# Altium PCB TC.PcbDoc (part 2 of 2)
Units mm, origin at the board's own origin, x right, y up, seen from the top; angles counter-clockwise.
Board outline 53.6 x 100 mm, 2 copper layers (Top Layer, Bottom Layer), stack 1.554 mm thick; 127 components, 95 nets, 328 pads, 171 vias.
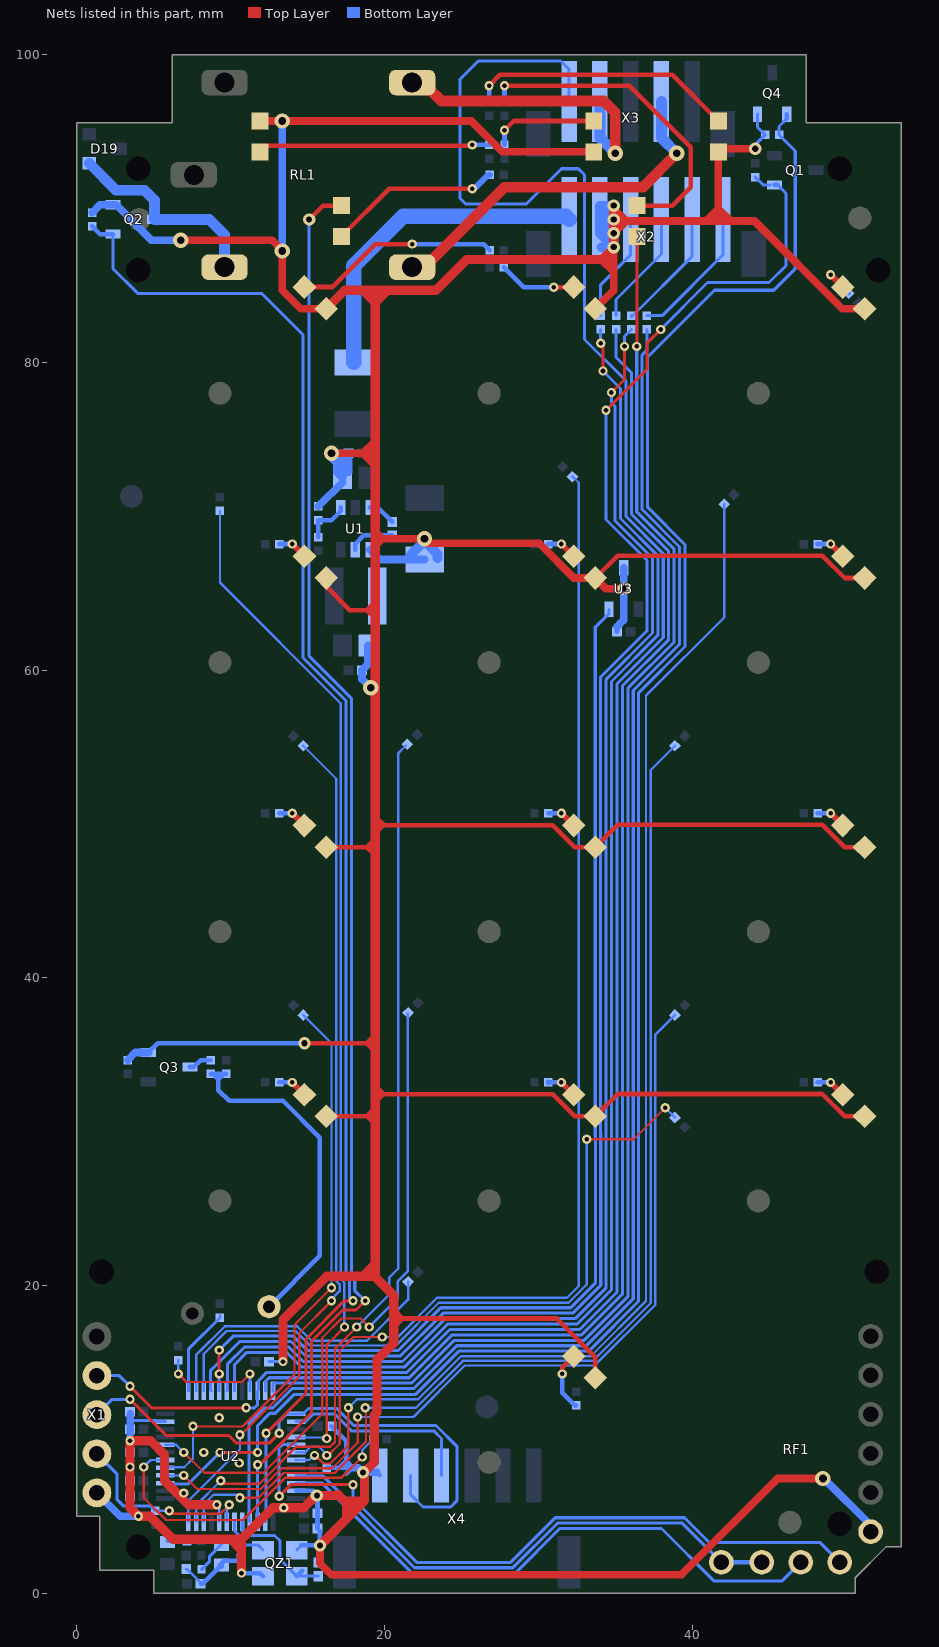
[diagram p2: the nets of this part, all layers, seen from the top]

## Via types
v1: diameter 0.6, hole 0.3, Top Layer to Bottom Layer, tented both sides, 82 vias
v2: diameter 0.8, hole 0.4, Top Layer to Bottom Layer, tented both sides, 64 vias
v3: diameter 0.5, hole 0.3, Top Layer to Bottom Layer, tented both sides, 13 vias
v4: diameter 1, hole 0.5, Top Layer to Bottom Layer, tented both sides, 12 vias

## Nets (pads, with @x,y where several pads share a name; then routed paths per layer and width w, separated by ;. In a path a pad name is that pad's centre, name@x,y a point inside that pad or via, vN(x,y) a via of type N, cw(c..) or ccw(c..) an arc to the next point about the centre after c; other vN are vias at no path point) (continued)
GND: C2.1 C3.1 C4.2 C5.1 C6.1 C7.1 C8.1 C9.1 C10.1 C11.1 C12.1 C13.1 C14.1 C15.1 C16.1 C17.1 C18.1 C19.1 C20.1 D3.2 D4.2 D5.2 D6.2 D7.2 D8.2 D9.2 D10.2 D11.2 D12.2 D13.2 D14.2 D15.2 D16.2 D17.2 D18.2 D21.1 Q2.3 Q3.3 Q4.3 QZ1.2 QZ1.4 R3.1 R34.2 R41.1 R42.2 R47.2 RF1.10 U1.1 U2.8 U2.23 U2.47 U3.1 X1.5 X2.2 X4.1 | length 522.7
  Top Layer w0.152: v2(18.6,7.85) 18.63,7.82 v2@18.702,7.748
  Top Layer w0.2: D5.2@41.7,93.7 D5.2@41.9,93.9
  Top Layer w0.3: v2(14.8,35.75) 18.848,35.75 ; D11.2@16.207,30.993 18.86,30.993 ; D10.2@16.207,48.493 18.857,48.493 ; D9.2@16.207,65.993 16.207,65.443 17.75,63.9 18.85,63.9 ; v4(19.1,58.85) v4@19.398,58.85 ; 19.35,48 18.857,48.493 ; 19.352,30.5 18.86,30.993 ; 19.398,31 19.39,30.993 18.86,30.993 ; 19.398,31.902 19.921,32.425 ; 19.398,32.45 19.422,32.425 19.921,32.425 ; 19.398,35.2 18.848,35.75 ; 19.398,35.8 19.348,35.75 18.848,35.75 ; 19.398,36.3 18.848,35.75 ; 19.398,48.5 19.39,48.493 18.857,48.493 ; 19.398,49.048 18.85,48.5 18.857,48.493 ; 19.398,49.402 19.921,49.925 ; 19.398,63.4 19.35,63.4 18.85,63.9 ; 19.398,63.9 18.85,63.9 ; 19.398,64.5 19.398,64.448 18.85,63.9 ; 19.398,68.6 19.4,68.6 ; 19.4,31.548 19.398,31.545 18.852,31 18.86,30.993 ; 19.422,49.925 19.921,49.925 ; 19.445,32.95 19.945,32.45 19.921,32.425 ; 19.445,50.45 19.945,49.95 19.921,49.925 ; 19.477,68.027 20,68.55 19.5,69.05 ; 20.55,18.4 20.6,18.35 ; 20.6,17.25 21.2,17.85 ; 20.6,17.85 21.2,17.85 ; 20.6,18.45 21.2,17.85 ; D18.2@33.707,13.993 33.707,15.34 31.197,17.85 21.2,17.85 ; D15.2@33.707,65.993 35.164,67.45 48.45,67.45 49.907,65.993 D14.2@51.207,65.993 ; D13.2@51.207,30.993 49.907,30.993 48.45,32.45 35.164,32.45 D17.2@33.707,30.993 32.357,30.993 30.925,32.425 19.921,32.425 ; D12.2@51.207,48.493 49.907,48.493 48.45,49.95 35.164,49.95 D16.2@33.707,48.493 32.357,48.493 30.925,49.925 19.921,49.925
  Top Layer w0.5: v4(6.75,87.95) 12.7,87.95 13.35,87.3 v4(13.35,87.25) 13.35,84.7 14.557,83.493 D6.2@16.207,83.493 ; D4.2@11.9,95.7 v4(13.35,95.7) 25.65,95.7 27.65,93.7 D3.2@33.6,93.7 ; v2(15.8,3.1) 15.8,1.95 16.548,1.202 39.302,1.202 45.55,7.45 v4(48.5,7.45) ; v4(16.55,74.1) 18.602,74.1 ; 19.302,73.4 18.602,74.1 ; 19.398,73.298 19.4,73.3 ; 19.4,68.6 19.45,68.55 20,68.55 v4(22.6,68.55) ; 19.4,74.1 19.398,74.1 18.602,74.1 ; 19.4,74.898 19.398,74.895 18.602,74.1 ; 20.6,18.35 20.6,18.45 ; v4@22.6,68.339 22.691,68.248 30.052,68.248 32.307,65.993 D15.2@33.707,65.993 34.4,65.3 v2(35.55,65.3) ; D7.2@33.707,83.493 34.9,84.686 34.9,85.9 ; v2(34.9,88.4) 35.7,89.2 ; v2(34.9,89.3) 35,89.2 35.7,89.2 ; v2(34.9,90.2) 34.9,90 35.7,89.2 ; D5.2@41.7,93.7 41.7,90 ; D5.2@41.9,93.9 v2(44.1,93.9) ; D8.2@51.207,83.493 49.757,83.493 44.05,89.2 42.5,89.2 ; 34.1,86.7 34.8,86.7 34.9,86.8 ; 34.1,86.7 34.9,85.9 ; 34.1,86.7 v2(34.9,87.5) 34.9,86.8 ; 34.9,85.9 34.9,86.8 ; 35.7,89.2 41,89.2 ; 41,89.2 41.7,89.2 ; 41,89.2 41,89.3 41.7,90 ; 41.7,89.2 41.7,90 ; 41.7,89.2 42.5,89.2 ; 41.7,90 42.5,89.2
  Top Layer w0.6: v1(9.1,5.75) 7.25,5.75 5.7,7.3 5.7,9 4.8,9.9 v1(3.45,9.9) v1(3.45,8.2) 3.45,5.55 v1(4,5) 4.75,5 6.25,3.5 10,3.5 ; v1(10.7,1.3) 10.7,2.8 ; v1(13.4,15.05) 13.4,17.764 16.238,20.602 18.6,20.602 ; v2(15.8,3.1) 18.05,5.35 ; D6.2@16.207,83.493 17.414,84.7 18.6,84.7 ; 17.534,4.976 17.534,5.866 ; v2@18.63,7.82 19.329,8.518 19.329,11.565 19.502,11.738 19.502,15.152 20.6,16.25 20.6,16.336 20.602,16.338 20.602,16.962 20.6,16.964 20.6,17.25 20.6,17.85 20.6,18.35 ; 18.666,5.966 18.63,5.966 ; v2@18.702,7.748 18.702,6.038 18.63,5.966 ; 19.398,64.448 19.398,63.9 19.398,63.4 19.398,58.85 19.398,49.402 19.398,49.048 19.398,48.5 19.398,36.3 19.398,35.8 19.398,35.2 19.398,32.45 19.398,31.902 19.398,31.545 19.398,31 19.398,21.4 ; 19.398,64.5 19.398,68.6 19.398,73.298 19.398,74.1 19.398,74.895 19.398,83.902 ; 19.4,83.9 20.198,84.698 ; 19.45,20.5 20.6,19.35 20.6,18.45 ; 34.1,86.7 25.35,86.7 23.35,84.7 19.398,84.7 ; v2(34.9,87.5) v2@34.9,90 ; 10,3.5 10.7,3.5 ; 10,3.5 10.7,2.8 ; 10.7,2.8 10.7,3.5 ; 10.7,3.5 12.748,5.548 v1(13.45,5.548) 14.748,5.548 15.55,6.35 v2(15.6,6.35) 16.95,6.35 17,6.4 17.534,5.866 ; 17.534,5.866 18.05,5.35 ; 17.534,5.866 17.534,5.966 18.63,5.966 ; 18.05,5.35 18.63,5.93 18.63,5.966 ; 18.6,20.602 19.398,21.4 ; 18.6,20.602 19.398,20.602 19.398,21.4 ; 18.6,84.7 19.398,84.7 ; 18.6,84.7 19.398,83.902 ; 19.398,83.902 19.398,84.7
  Bottom Layer w0.152: 3.46,11.2 3.51,11.15 ; C7.1@7.1,1.56 7.163,1.56 8.04,0.683 C6.1@8.04,0.6 ; v1(9.1,5.75) 9.25,5.6 U2.8@9.25,4.65
  Bottom Layer w0.2: v1(3.45,8.2) v1@3.46,8.21 ; v1(3.45,9.9) v1@3.46,9.91 ; 3.51,11.15 3.572,11.212 5.138,11.212 5.2,11.15 U2.23@5.75,11.15 ; C15.1@12.49,15.05 v1(13.4,15.05) ; QZ1.2@14.3,2.8 QZ1.2@14.6,3.1 ; v2(15.6,6.35) 15.6,6.3 v2@15.64,6.26 ; v2(44.1,93.9) 44.1,94.15 R47.2@44.75,94.8 44.25,95.3 Q4.3@44.25,96.15
  Bottom Layer w0.3: Q3.3@4.65,35.15 5.25,35.75 v2(14.8,35.75) ; C6.1@8.04,0.6 8.175,0.6 C8.1@9.35,1.775 ; C8.1@9.4,1.725 C8.1@9.35,1.775 ; C8.1@9.4,1.825 C8.1@9.35,1.775 ; QZ1.4@12.1,1.1 11.9,1.3 v1(10.7,1.3) C18.1@10.7,2.26 10.54,2.1 9.575,2.1 9.3,1.825 C8.1@9.35,1.775 ; U2.47@14.25,6.65 15.35,6.65 15.6,6.4 v2(15.6,6.35) ; QZ1.2@14.6,3.1 v2(15.8,3.1) ; v2@15.64,6.26 C10.1@15.64,5.2 C9.1@15.64,4.2 15.8,4.04 v2(15.8,3.1) ; C19.1@15.7,1.98 15.7,3 v2(15.8,3.1) ; R34.2@16.25,8.15 17.5,8.15 ; C16.1@16.54,10.85 17.5,9.89 17.5,8.6 ; 17.1,8.2 17.5,8.6 ; C2.1@17.275,72.225 C2.1@17.275,72.5 C2.1@17.66,72.885 ; 17.5,7.75 17.9,8.15 ; X4.1@19.5,7.85 X4.1@19.7,7.65 ; C20.1@35.11,62.5 35.11,62.81 ; 17.5,8.15 17.5,8.6 ; 17.5,8.15 17.9,8.15 ; 17.5,8.6 17.9,8.2 17.9,8.15
  Bottom Layer w0.5: R41.1@1,89.75 1.5,90.25 Q2.3@2.35,90.25 2.55,90.25 4.85,87.95 v4(6.75,87.95) ; X1.5@1.3,6.52 2.82,5 v1(4,5) ; R42.2@3.3,34.65 3.8,35.15 Q3.3@4.65,35.15 ; C12.1@3.46,6.3 C13.1@3.46,7.3 3.46,8.21 C14.1@3.46,9.15 3.46,9.91 C17.1@3.46,10.65 3.46,11.2 C11.1@3.46,11.65 ; v4(13.35,87.25) v4(13.35,95.7) ; R3.1@15.7,70.65 C2.1@17.275,72.225 ; C2.1@16.9,72.875 C2.1@17.25,72.525 ; C2.1@16.9,73.1 16.9,73.45 ; C2.1@17.275,72.5 C2.1@17.25,72.525 ; C2.1@17.66,72.885 C3.1@17.66,74.1 17.25,74.1 ; 17.9,8.15 18.3,8.15 v2(18.6,7.85) X4.1@19.5,7.85 ; C4.2@18.925,61.6 18.925,60.385 C5.1@18.54,60 18.54,59.41 v4(19.1,58.85) ; U1.1@19.05,67.825 19.675,67.2 D21.1@22.6,67.2 ; 35.11,62.81 35.258,62.958 35.258,62.977 35.493,63.212 35.512,63.212 35.55,63.25 v2(35.55,65.3) U3.1@35.55,66.65 ; v4(48.5,7.45) 48.55,7.45 51.6,4.4 RF1.10@51.6,4 ; v4(16.55,74.1) 16.55,73.8 16.9,73.45 ; v4(16.55,74.1) 17.25,74.1 ; v4(16.55,74.1) 16.9,73.75 16.9,73.45 ; C2.1@17.25,72.525 17.25,74.1
  Bottom Layer w0.635: D21.1@21.7,67.5 22.6,68.4 23.45,67.55 D21.1@23.45,67.3 ; X2.2@34,88.4 v2(34.9,87.5) ; X2.2@34.1,87.5 v2(34.9,87.5) ; X2.2@34,89.3 v2(34.9,90.2) ; X2.2@34,89.3 v2(34.9,88.4) ; X2.2@34,89.3 v2(34.9,89.3) ; X2.2@34,89.3 34,90.2 v2(34.9,90.2) ; X2.2@34,89.3 34,88.5 34.1,88.4 v2(34.9,88.4) ; v2(34.9,87.5) v2(34.9,88.4) ; v2(34.9,88.4) v2(34.9,89.3) ; v2(34.9,89.3) v2(34.9,90.2)
  other v1: 6.95,6.5 10.55,8.45 8.25,9.15 9.25,11.4
LED_A_DEN_1: D1.2 U2.36 | length 97.2
  Top Layer w0.2: v1(36.4,81.05) 36.402,81.052 36.402,88.198 D1.2@36.4,88.2
  Bottom Layer w0.2: U2.36@12.75,13.105 U2.36@12.75,13.15 12.75,13.65 21.753,13.65 24.539,16.436 32.976,16.436 35.817,19.277 35.817,30.605 35.814,30.607 35.814,58.823 38.824,61.833 38.824,67.867 36.398,70.294 v1@36.398,81.1
LED_A_GRA_1: D2.2 U2.3 | length 92.5
  Top Layer w0.2: v1(11.75,8.35) 11.75,8.281 11.781,8.25 15.25,11.719 15.25,16.365 17.285,18.4 18.15,18.4 v1(18.75,19)
  Top Layer w0.3: v2(15.1,89.3) 16,90.2 D2.2@17.2,90.2
  Bottom Layer w0.2: U2.3@11.75,4.65 11.75,8.05 v1(11.75,8.35) ; v2(15.1,89.3) 15.1,60.912 17.841,58.172 17.841,20.701 18.064,20.477 18.064,19.667 v1@18.731,19 ; v1@18.6,19 v1@18.731,19 ; v1@18.741,18.991 v1@18.731,19 ; v1@18.85,19 v1@18.731,19
LED_BACKLIGHT_1: Q1.2 R37.1 U2.28 | length 112.4
  Top Layer w0.2: v1(34.4,76.9) 37.05,79.55 37.05,81.25 v1(37.95,82.15)
  Bottom Layer w0.2: U2.28@8.75,13.15 8.698,13.202 8.698,14.479 9.021,14.802 9.034,14.802 10.586,16.355 13.923,16.355 14.866,15.412 21.023,15.412 23.809,18.198 32.246,18.198 34.055,20.006 34.055,29.875 34.052,29.877 34.052,59.552 37.062,62.563 37.062,67.138 34.4,69.8 v1(34.4,76.9) ; v1(37.95,82.15) 41,85.2 45,85.2 46.1,86.3 46.1,91 Q1.2@45.55,91.55 ; R37.1@44.1,92.05 44.6,91.55 Q1.2@45.05,91.55
  Bottom Layer w0.3: Q1.2@45.35,91.55 Q1.2@45.55,91.55
M_125K_1: RF1.3 U2.41 | length 46.1
  Top Layer w0.2: v1(13.15,6.3) 13.902,7.052 13.905,7.05 v1(17.95,7.05)
  Bottom Layer w0.2: v1(13.15,6.3) 13.15,9.45 13.35,9.65 U2.41@14.25,9.65 ; v1(17.95,7.05) 17.95,6.147 22.097,2 28.196,2 31.096,4.9 39.498,4.9 41.098,3.3 48.3,3.3 RF1.3@49.6,2
M_BELL_1: Q4.2 R47.1 U2.15 | length 123
  Top Layer w0.2: v1(9.3,9.15) v1(11.75,9.15)
  Bottom Layer w0.2: U2.15@5.75,7.15 5.802,7.098 7.248,7.098 v1(9.3,9.15) ; v1(11.75,9.15) 11.748,9.152 11.748,10.898 12.545,11.695 12.901,11.695 14.129,12.924 22.024,12.924 24.831,15.731 33.268,15.731 36.522,18.985 36.522,30.897 36.519,30.899 36.519,58.531 39.529,61.541 39.529,68.159 37.102,70.586 37.102,80.354 41.448,84.7 45.3,84.7 46.7,86.1 46.7,93.75 R47.1@45.65,94.8 45.65,95.35 Q4.2@46.15,95.85
  Bottom Layer w0.3: Q4.2@46.15,95.85 Q4.2@46.15,96.15
M_CAPKEY1_1: R6.1 U2.40 | length 66.2
  Top Layer w0.152: v1(16.25,10.05) 16.25,16.15 v1(17.4,17.3)
  Bottom Layer w0.152: R6.1@9.3,70.35 9.3,65.7 17.16,57.84 17.16,20.419 17.383,20.195 17.383,19.505 ; U2.40@14.25,10.15 14.25,10.111 16.189,10.111 v1(16.25,10.05) ; 17.383,19.504 17.383,17.317 v1(17.4,17.3)
M_CAPKEY2_1: R16.1 U2.42 | length 79.7
  Top Layer w0.152: v1(16.25,8.95) 16.329,8.95 17.083,9.705 17.083,15.752 17.981,16.65 v1(19.85,16.65)
  Bottom Layer w0.152: U2.42@14.25,9.15 14.823,9.15 15.202,9.529 15.721,9.529 16.25,9 v1(16.25,8.95) ; v1(19.85,16.65) 20.867,16.65 23.417,19.2 31.854,19.2 32.621,19.967 32.621,72.179 R16.1@32.218,72.582
M_CAPKEY3_1: R17.1 U2.43 | length 82.8
  Top Layer w0.152: v1(15.45,8.95) 15.502,8.95 16.031,8.421 16.471,8.421 17.65,9.6 v1(17.65,12.05)
  Bottom Layer w0.152: U2.43@14.25,8.65 14.25,8.654 15.104,8.654 15.4,8.95 v1(15.45,8.95) ; v1(17.65,12.05) 18.195,12.595 22.16,12.595 24.967,15.402 33.404,15.402 36.998,18.996 36.998,58.348 42.082,63.432 R17.1@42.082,70.782
  Bottom Layer w0.2: U2.43@14.25,8.654 U2.43@14.25,8.677
M_CAPKEY4_1: R18.1 U2.12 | length 55.5
  Top Layer w0.152: v1(10.6,10.3) 10.671,10.3 14.45,14.079 14.45,16.9 v1(16.55,19)
  Bottom Layer w0.152: U2.12@7.25,4.65 7.25,6 10.6,9.35 v1(10.6,10.3) ; R18.1@14.718,55.082 16.855,52.945 16.855,20.293 17.079,20.069 17.079,19.631 16.55,19.102 16.55,19.1 v1(16.55,19)
M_CAPKEY5_1: R19.1 U2.11 | length 59.1
  Top Layer w0.152: v1(9.35,7.3) 9.55,7.1 11.852,7.1 14.274,9.521 16.469,9.521 16.779,9.831 16.779,15.879 v1(18.2,17.3)
  Bottom Layer w0.152: U2.11@7.75,4.65 7.75,5.7 v1(9.35,7.3) ; v1(18.2,17.3) 20.3,19.4 20.3,20.5 20.881,21.081 20.881,54.581 R19.1@21.382,55.082
M_CAPKEY6_1: R20.1 U2.10 | length 74
  Top Layer w0.152: v1(10.6,6.2) 11.815,6.2 13.426,7.812 16.762,7.812 18.8,9.85 18.8,12 v1(18.75,12.05)
  Bottom Layer w0.152: U2.10@8.25,4.65 8.25,5.769 8.881,6.4 10.4,6.4 v1(10.6,6.2) ; v1(18.75,12.05) 22.046,12.05 25.093,15.097 33.53,15.097 37.302,18.87 37.302,53.502 R20.1@38.882,55.082
M_CAPKEY7_1: R21.1 U2.17 | length 37.3
  Top Layer w0.152: v1(7.55,10.85) 7.543,10.85 7.521,10.829 10.769,10.829 14.145,14.205 14.145,17.445 v1(16.55,19.85)
  Bottom Layer w0.152: U2.17@5.75,8.15 5.779,8.179 6.979,8.179 7.55,8.75 v1(7.55,10.85) ; R21.1@14.718,37.582 16.55,35.75 v1(16.55,19.85)
M_CAPKEY8_1: R22.1 U2.20 | length 42.7
  Top Layer w0.152: v1(6.95,9.15) 8.279,7.821 9.124,7.821 9.131,7.829 9.569,7.829 9.576,7.821 11.969,7.821 11.976,7.829 12.129,7.829 15.945,11.645 15.945,16.595 17.2,17.85 18.45,17.85 v1(19,17.3)
  Bottom Layer w0.152: U2.20@5.75,9.65 6.45,9.65 v1(6.95,9.15) ; v1(19,17.3) 20.85,19.15 20.85,20.262 21.5,20.912 21.5,37.664 R22.1@21.482,37.682
M_CAPKEY9_1: R30.1 U2.16 | length 57.5
  Top Layer w0.152: v1(6.95,7.65) 7.829,6.771 11.955,6.771 13.3,8.117 16.598,8.117 18.25,9.769 v1(18.25,11.45)
  Bottom Layer w0.152: U2.16@5.75,7.65 v1(6.95,7.65) ; v1(18.25,11.45) 21.877,11.45 25.219,14.793 33.656,14.793 37.607,18.743 37.607,36.307 R30.1@38.882,37.582
M_CAPKEY10_1: R31.1 U2.25 | length 5.7
  Bottom Layer w0.2: U2.25@7.25,13.15 7.25,15.85 R31.1@9.3,17.9 R31.1@9.3,18.05
M_CAPKEY11_1: R32.1 U2.26 | length 19.5
  Bottom Layer w0.152: U2.26@7.75,13.15 7.75,15.481 9.61,17.341 14.331,17.341 15.274,16.398 18.848,16.398 21.532,19.082 R32.1@21.532,20.232
M_CAPKEY12_1: R33.1 U2.27 | length 46.2
  Top Layer w0.152: v1(33.15,29.5) 36.2,29.5 v1(38.25,31.55)
  Bottom Layer w0.152: U2.27@8.25,13.15 8.25,15.55 9.736,17.036 14.205,17.036 15.148,16.093 20.741,16.093 23.527,18.879 31.964,18.879 33.15,20.065 v1(33.15,29.5) ; v1(38.25,31.55) R33.1@38.882,30.918
M_CAPKEY13_1: R35.1 U2.18 | length 21.7
  Top Layer w0.152: v1(4.35,8.2) 4.5,8.2 4.35,8.05 4.35,6.2 5.8,4.75 10.8,4.75 13.557,7.507 17.207,7.507 v1(18.55,8.85)
  Bottom Layer w0.152: v1(4.35,8.2) 4.761,8.611 4.765,8.611 4.803,8.65 U2.18@5.75,8.65 ; v1(18.55,8.85) 18.55,9.3 R35.1@19.25,10
M_CAPSHIELD_1: R36.1 U2.33 | length 7.1
  Top Layer w0.152: v1(6.6,14.25) 7.129,13.721 10.721,13.721 v1(11.25,14.25)
  Bottom Layer w0.152: v1(6.6,14.25) R36.1@6.6,15.15
  Bottom Layer w0.2: U2.33@11.25,13.15 v1(11.25,14.25)
M_SCL_1: RF1.5 RF1.6 U2.45 | length 35
  Bottom Layer w0.2: U2.45@14.25,7.65 14.75,7.65 14.777,7.623 15.976,7.623 21.951,1.648 28.342,1.648 31.242,4.548 39.352,4.548 RF1.6@41.9,2
  Bottom Layer w0.3: RF1.6@41.9,2 RF1.5@44.52,2
M_SDA_1: RF1.4 U2.46 | length 38.3
  Bottom Layer w0.2: U2.46@14.25,7.15 15.95,7.15 21.805,1.295 28.488,1.295 31.388,4.195 38.005,4.195 41.4,0.8 45.86,0.8 RF1.4@47.06,2
M_WIN0_RX_1: R43.1 U2.31 | length 94.2
  Top Layer w0.2: v1(34.05,81.25) 34.2,81.1 v1(34.2,79.45)
  Bottom Layer w0.2: U2.31@10.25,13.15 10.25,14.85 11.05,15.65 13.631,15.65 14.574,14.707 21.315,14.707 24.101,17.493 32.538,17.493 34.76,19.714 34.76,30.167 34.757,30.169 34.757,59.26 37.767,62.271 37.767,67.429 35.34,69.856 35.34,78.31 v1(34.2,79.45) ; v1(34.05,81.25) R43.1@34.05,82.15
M_WIN1_1: R45.1 U2.35 | length 91.6
  Bottom Layer w0.2: U2.35@12.25,13.15 12.25,13.757 12.495,14.002 21.607,14.002 24.393,16.788 32.83,16.788 35.464,19.423 35.464,30.459 35.462,30.461 35.462,58.969 38.472,61.979 38.472,67.721 36.045,70.148 36.045,79.355 35.048,80.352 35.048,82.148 R45.1@35.05,82.15
M_WOUT0_TX_1: R44.1 U2.30 | length 94.4
  Top Layer w0.2: v1(34.75,78.05) 35.6,78.9 v1(35.6,81.05)
  Bottom Layer w0.2: U2.30@9.75,13.15 9.802,13.202 9.802,14.901 10.904,16.002 13.777,16.002 14.72,15.06 21.169,15.06 23.955,17.845 32.392,17.845 34.407,19.86 34.407,30.021 34.405,30.023 34.405,59.406 37.415,62.417 37.415,67.283 34.988,69.71 34.988,77.162 34.75,77.4 v1(34.75,78.05) ; v1(35.6,81.05) 35.6,81.7 R44.1@36.05,82.15
M_WOUT1_1: R46.1 U2.4 | length 100.1
  Bottom Layer w0.2: U2.4@11.25,4.65 11.198,4.702 11.198,11.048 12.198,12.048 12.755,12.048 14.005,13.298 21.899,13.298 24.685,16.083 33.122,16.083 36.169,19.131 36.169,30.751 36.167,30.753 36.167,58.677 39.177,61.687 39.177,68.013 36.75,70.44 36.75,80.5 37.05,80.8 R46.1@37.05,82.15
NC_1: RL1.4 X3.4 | length 24.1
  Top Layer w0.7: RL1.4@21.8,86.2 22.6,86.2 27.8,91.4 36.8,91.4 v4(39,93.6)
  Bottom Layer w0.7: X3.4@38,96.975 38,94.6 v4(39,93.6)
NetBZ1_2: BZ1.2 R38.1 R39.2 | length 23.9
  Bottom Layer w0.3: R39.2@8.7,33.75 R39.2@8.85,33.75 ; R38.1@9.7,33.75 R38.1@9.55,33.75 ; BZ1.2@12.5,18 12.5,18.627 15.8,21.927 15.8,29.6 13.4,32 9.9,32 9.2,32.7 9.2,33.4 ; R39.2@8.85,33.75 9.2,33.75 ; R39.2@8.85,33.75 9.2,33.4 ; 9.2,33.4 9.2,33.75 ; 9.2,33.4 R38.1@9.55,33.75 ; 9.2,33.75 R38.1@9.55,33.75
NetC1_1: C1.1 L1.1 U1.2 | length 3
  Bottom Layer w0.3: U1.2@18.1,67.825 18.1,68.2 18.66,68.76 C1.1@20.5,68.76
NetC1_2: C1.2 U1.6 | length 1.8
  Bottom Layer w0.3: U1.6@19.05,70.575 19.565,70.575 C1.2@20.5,69.64
NetC8_2: C8.2 R2.1 | length 2.3
  Bottom Layer w0.2: R2.1@8.1,1.55 R2.1@8.107,1.55 ; R2.1@8.197,1.55 R2.1@8.107,1.55 ; C8.2@9.4,3.175 8.627,2.402 8.627,2.07 R2.1@8.107,1.55
NetD1_1: D1.1 R4.2 | length 21.4
  Top Layer w0.3: v1(27.8,98) 35.9,98 39.904,93.996 39.904,91.404 38.7,90.2 D1.1@36.4,90.2
  Bottom Layer w0.3: R4.2@27.8,96.95 v1(27.8,98)
NetD2_1: D2.1 R5.2 | length 11.3
  Top Layer w0.3: D2.1@17.2,88.2 20.3,91.3 v1(25.7,91.3)
  Bottom Layer w0.381: v1@25.775,91.225 26.75,92.2 R5.2@26.85,92.2
NetD3_1: D3.1 R9.1 | length 7
  Top Layer w0.3: v1(27.8,95.1) 28.4,95.7 D3.1@33.6,95.7
  Bottom Layer w0.3: R9.1@27.8,94.15 v1(27.8,95.1)
NetD4_1: D4.1 R7.1 | length 15.1
  Top Layer w0.3: D4.1@11.9,93.7 12.3,94.1 25.65,94.1 v1(25.7,94.15)
  Bottom Layer w0.3: v1(25.7,94.15) R7.1@26.8,94.15
NetD5_1: D5.1 R8.1 | length 17.5
  Top Layer w0.3: v1(26.8,98) 27.5,98.7 38.7,98.7 D5.1@41.7,95.7
  Bottom Layer w0.3: R8.1@26.8,96.95 v1(26.8,98)
NetD6_1: D6.1 R10.1 | length 13.4
  Top Layer w0.3: D6.1@14.793,84.907 16.607,84.907 19.4,87.7 v1(21.8,87.7)
  Bottom Layer w0.3: v1(21.8,87.7) 26.45,87.7 R10.1@26.85,87.3
NetD7_1: D7.1 R11.1 | length 5.1
  Top Layer w0.3: v1(31,84.9) 32.286,84.9 D7.1@32.293,84.907
  Bottom Layer w0.3: R11.1@27.75,86.2 29.05,84.9 v1(31,84.9)
NetD8_1: D8.1 R12.1 | length 2.8
  Top Layer w0.381: v1(49,85.7) D8.1@49.793,84.907
  Bottom Layer w0.3: v1(49,85.7) R12.1@50.182,84.518
NetD9_1: D9.1 R13.1 | length 2
  Top Layer w0.381: v1(14,68.2) D9.1@14.793,67.407
  Bottom Layer w0.3: R13.1@13.15,68.2 v1(14,68.2)
NetD10_1: D10.1 R14.1 | length 2
  Top Layer w0.381: v1(14,50.7) D10.1@14.793,49.907
  Bottom Layer w0.3: R14.1@13.15,50.7 v1(14,50.7)
NetD11_1: D11.1 R15.1 | length 2
  Top Layer w0.381: v1(14,33.2) D11.1@14.793,32.407
  Bottom Layer w0.3: R15.1@13.15,33.2 v1(14,33.2)
NetD12_1: D12.1 R23.1 | length 2
  Top Layer w0.381: v1(49,50.7) D12.1@49.793,49.907
  Bottom Layer w0.3: R23.1@48.15,50.7 v1(49,50.7)
NetD13_1: D13.1 R29.1 | length 2
  Top Layer w0.381: v1(49,33.2) D13.1@49.793,32.407
  Bottom Layer w0.3: R29.1@48.15,33.2 v1(49,33.2)
NetD14_1: D14.1 R24.1 | length 2
  Top Layer w0.381: v1(49,68.2) D14.1@49.793,67.407
  Bottom Layer w0.3: R24.1@48.15,68.2 v1(49,68.2)
NetD15_1: D15.1 R25.1 | length 2
  Top Layer w0.381: v1(31.5,68.2) D15.1@32.293,67.407
  Bottom Layer w0.3: R25.1@30.65,68.2 v1(31.5,68.2)
NetD16_1: D16.1 R26.1 | length 2
  Top Layer w0.381: v1(31.5,50.7) D16.1@32.293,49.907
  Bottom Layer w0.3: R26.1@30.65,50.7 v1(31.5,50.7)
NetD17_1: D17.1 R27.1 | length 2
  Top Layer w0.381: v1(31.5,33.2) D17.1@32.293,32.407
  Bottom Layer w0.3: R27.1@30.65,33.2 v1(31.5,33.2)
NetD18_1: D18.1 R28.1 | length 3.9
  Top Layer w0.3: v1(31.55,14.25) 31.55,14.664 D18.1@32.293,15.407
  Bottom Layer w0.3: v1(31.55,14.25) 31.55,13.022 32.372,12.2 R28.1@32.45,12.2
NetD19_1: D19.1 Q2.1 RL1.5 | length 13.6
  Bottom Layer w0.7: D19.1@0.8,92.95 2.55,91.2 4.4,91.2 5.05,90.55 Q2.1@5.05,89.3 8.6,89.3 9.6,88.3 RL1.5@9.6,86.2
NetD20_1: D20.1 X2.1 | length 21.7
  Bottom Layer w1: D20.1@18,80 18,86.3 21.198,89.498 29.532,89.498 29.535,89.5 31.8,89.5 X2.1@32,89.3
NetFB1_1: FB1.1 L2.2 | length 1.3
  Bottom Layer w0.2: L2.2@5.9,3.415 L2.2@5.915,3.4
  Bottom Layer w0.3: L2.2@5.915,3.4 FB1.1@7.145,3.4
NetQ3_1: Q3.1 R39.1 | length 1.5
  Bottom Layer w0.3: Q3.1@7.35,34.2 7.6,34.2 8.05,34.65 R39.1@8.7,34.65
NetR1_1: R1.1 R3.2 U1.4 | length 3
  Bottom Layer w0.3: R1.1@15.7,68.65 R3.2@15.7,69.75 16.55,69.75 17.15,70.35 U1.4@17.15,70.575
NO_1: RL1.3 X3.2 | length 21.6
  Top Layer w0.7: v4(35,93.6) 35,96.254 34.254,97 23.7,97 RL1.3@22.8,97.9 ; RL1.3@22.8,97.9 22.1,97.9 RL1.3@21.8,98.2 22.5,98.2 RL1.3@22.8,97.9
  Bottom Layer w0.7: X3.2@34,96.975 34,94.6 v4(35,93.6)
OSC_IN_1: C19.2 QZ1.3 U2.5 | length 8
  Bottom Layer w0.2: U2.5@10.75,4.65 10.75,4.043 11.043,3.75 12.85,3.75 13.2,3.4 13.2,2.2 QZ1.3@14.3,1.1 C19.2@15.7,1.1
  Bottom Layer w0.3: QZ1.3@14.3,1.1 QZ1.3@14.66,1.46
OSC_OUT_1: C18.2 QZ1.1 U2.6 | length 3.2
  Bottom Layer w0.2: U2.6@10.25,4.65 10.25,4.043 10.495,3.798 10.497,3.798 10.7,3.595 C18.2@10.7,3.14 11.76,3.14 QZ1.1@12.1,2.8
RELAY_1: Q2.2 R41.2 U2.2 | length 99.1
  Top Layer w0.2: v1(12.3,10.4) 14.898,12.998 14.898,16.511 17.387,19 v1(17.95,19)
  Bottom Layer w0.2: Q2.2@2.35,88.35 2.35,86.1 3.95,84.5 12,84.5 14.7,81.8 14.7,60.814 17.488,58.026 17.488,20.555 17.712,20.331 17.712,19.369 ; U2.2@12.25,4.65 12.302,4.702 v1(12.3,10.4) v1(12.3,10.4) ; 17.711,19.368 17.711,19.239 v1(17.95,19)
  Bottom Layer w0.3: R41.2@1,88.85 1.5,88.35 Q2.2@2.35,88.35
RESET_1: R40.1 U2.7 X1.4 | length 12.6
  Top Layer w0.152: v1(6,5.35) 6.2,5.15 9.3,5.15 v1(9.9,5.75)
  Bottom Layer w0.152: R40.1@5.1,5.35 v1(6,5.35) ; U2.7@9.75,4.65 9.75,5.6 v1(9.9,5.75)
  Bottom Layer w0.2: X1.4@1.3,9.06 2.6,7.76 2.6,6.1 3.05,5.65 4.8,5.65 R40.1@5.1,5.35 ; U2.7@9.75,4.65 U2.7@9.752,4.652
RX2_1: U2.38 X4.3 | length 12.7
  Bottom Layer w0.2: U2.38@14.25,11.15 14.857,11.15 15.357,11.65 16.752,11.65 17.856,10.545 23.205,10.545 23.7,10.05 X4.3@23.7,7.65
SWCLK_TX2_1: U2.37 X1.3 X4.2 | length 35.7
  Top Layer w0.2: v1(3.45,12.6) 5.8,10.25 9.869,10.25 10.371,9.748 12.498,9.748 v1(13.15,10.4)
  Bottom Layer w0.2: X1.3@1.3,11.6 2.3,12.6 v1(3.45,12.6) ; v1(13.15,10.4) 13.15,11.157 13.643,11.65 U2.37@14.25,11.65 14.7,11.65 15.052,12.002 16.898,12.002 18.002,10.898 23.351,10.898 24.7,9.548 24.7,6 24.3,5.6 22.5,5.6 21.7,6.4 X4.2@21.7,7.65
SWDIO_M_BT_1: U2.34 X1.2 X3.1 | length 141.7
  Top Layer w0.2: v1(3.45,13.45) 4.852,12.048 10.998,12.048 v1(11,12.05)
  Bottom Layer w0.2: X1.2@1.3,14.14 2.76,14.14 v1(3.45,13.45) ; v1@10.95,12.048 11.548,12.048 11.75,12.25 U2.34@11.75,13.15 11.802,13.202 11.802,13.809 12.348,14.355 21.461,14.355 24.247,17.14 32.684,17.14 35.112,19.569 35.112,30.313 35.11,30.315 35.11,59.114 38.12,62.125 38.12,67.575 35.693,70.002 35.693,78.807 33,81.5 33,92.2 32.6,92.6 31.5,92.6 29.2,90.3 25.3,90.3 24.9,90.7 24.9,98.4 26.1,99.6 31.45,99.6 32,99.05 X3.1@32,96.975
TAMPER_1: U2.29 U3.3 | length 73.9
  Top Layer w0.2: v1(9.25,14.25) v1(9.25,15.8)
  Bottom Layer w0.2: U2.29@9.25,13.15 v1(9.25,14.25) ; v1(9.25,15.8) 10.157,16.707 14.069,16.707 15.012,15.764 20.877,15.764 23.663,18.55 32.1,18.55 33.702,20.152 33.702,29.729 33.7,29.731 33.7,62.8 34.6,63.7 U3.3@34.6,63.95
WIN0_RX_1: R43.2 X2.3 | length 7.1
  Bottom Layer w0.2: R43.2@34.05,83.05 34.05,85.05 36,87 X2.3@36,89.3
WIN1_1: R45.2 X2.4 | length 7.5
  Bottom Layer w0.2: R45.2@35.05,83.05 35.05,84.1 38,87.05 X2.4@38,89.3
WOUT0_TX_1: R44.2 X2.5 | length 8.1
  Bottom Layer w0.2: R44.2@36.05,83.05 36.05,82.957 40,86.907 X2.5@40,89.3
WOUT1_1: R46.2 X2.6 | length 8.9
  Bottom Layer w0.2: R46.2@37.05,83.05 38.05,83.05 42,87 X2.6@42,89.3
pads on no net: D19.2 FID1.1 FID2.1 FID3.1 FID4.1 FID5.1 FID6.1 RF1.7 RF1.8 RF1.9 X2.P1 X2.P2 X3.P1 X3.P2 X4.5 X4.6 X4.P1 X4.P2

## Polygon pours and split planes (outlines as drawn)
GND on Bottom Layer "NONET_L-01_P-001" (solid, remove dead copper, pour order 23): -0.006,4.994 1.494,4.994 1.494,1.494 4.994,1.494 4.994,-0.006 16.4,-0.006 16.4,5.65 17.65,6.9 17.65,13.15 -0.006,13.15
GND on Bottom Layer "NONET_L-01_P-001" (solid, remove dead copper, pour order 19): 16.5,75 15.4,73.9 15.4,61.2 18.35,58.25 19.6,58.25 20.3,58.95 20.3,63.2 23.4,66.3 23.9,66.3 23.9,72.1 23.5,72.1 20.6,75
+3V3 on Bottom Layer "NONET_L-01_P-001" (solid, remove dead copper, pour order 6): 17.32,66.66 16.12,66.66 16.12,62.96 16.65,62.43 16.65,60.87 17.33,60.19 17.33,59.69 17.99,59.69 17.99,62.29 17.32,62.96
NetC1_1 on Bottom Layer "NONET_L-01_P-001" (solid, remove dead copper, pour order 2): 17.8,68.33 18.4,68.33 18.4,67.19 18.92,66.67 20.13,66.67 20.13,62.96 18.92,62.96 18.92,65.08 17.8,66.2
+12V on Bottom Layer "NONET_L-01_P-001" (solid, remove dead copper, pour order 0): 18.21,74.5 17.56,75.15 16.75,75.15 16.75,76.85 19.25,76.85 19.25,75.15 19.25,73.53 20.73,72.05 23.85,72.05 23.85,70.35 20.98,70.35 19.78,71.55 18.92,71.55 18.4,71.03 18.4,69.23 17.45,68.28 17.45,67.32 16.85,67.32 16.85,69.17 17.8,70.12 17.8,71.34 18.21,71.75 18.21,73.79
GND on Top Layer "NONET_L-01_P-001" (solid, remove dead copper, pour order 21): 0,5 1.5,5 1.5,1.5 5,1.5 5,0 12.5,0 13.9,1.4 13.9,3.15 16,5.25 16,13.1 0,13.1
CAPSHIELD_1 on Top Layer "NONET_L-01_P-001" (hatched 45Degree grid 1 track 0.152, remove dead copper, pour order 24): 1.5,1.5 5,1.5 5,0 50.6,0 50.6,1 52.6,3 53.6,3 53.6,81.1 46.75,87.95 6.2,87.95 0,87.95 0,5 1.5,5
GND on Top Layer "NONET_L-01_P-001" (solid, remove dead copper, pour order 26): 0,95.6 0,87.95 12.7,87.95 13.35,87.25 13.35,84.7 14.3,83.5 16.207,83.493 17.414,84.7 23.35,84.7 25.35,86.7 34.9,86.7 34.9,87.95 45.3,87.95 49.757,83.493 51.207,83.493 53.6,81.1 53.6,95.6 47.4,95.6 47.4,100 6.2,100 6.2,95.6

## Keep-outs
Top Layer:
  circle w0.203: c26.8,8.5 r6.5
  circle w0.203: c9.3,78 r6.5
  circle w0.203: c26.8,78 r6.5
  circle w0.203: c44.3,78 r6.5
  circle w0.203: c44.3,60.5 r6.5
  circle w0.203: c26.8,60.5 r6.5
  circle w0.203: c9.3,60.5 r6.5
  circle w0.203: c9.3,43 r6.5
  circle w0.203: c26.8,43 r6.5
  circle w0.203: c44.3,43 r6.5
  circle w0.203: c44.3,25.5 r6.5
  circle w0.203: c26.8,25.5 r6.5
  circle w0.203: c9.3,25.5 r6.5
  circle w0.152: c4.028,89.327 r1.263
  circle w0.203: c50.851,89.449 r1.263
  circle w0.203: c46.301,4.649 r1.263
Bottom Layer:
  circle w0.203: c3.501,71.251 r1.263
  circle w0.203: c50.878,89.401 r1.263
  circle w0.203: c26.601,12.051 r1.263
Keep-Out Layer:
  lines w0.1: 6.2,95.6 0,95.6 0,5 1.5,5 1.5,1.5 5,1.5 5,0 48.6,0 50.6,0 50.6,1 52.6,3 53.6,3 53.6,5 53.6,95.6 47.4,95.6 47.4,100 26.8,100 6.2,100 6.2,95.6 ; 6.2,95.6 6.2,95.6

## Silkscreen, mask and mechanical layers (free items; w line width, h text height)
Top Overlay:
  rectangle: 35,92.7 40.3,96.7
  rectangle: 13.3,92.7 32.2,96.7
  rectangle: 18.6,87.2 35,91.2
  text "Control iD" at 5.8,6.25 h1
  text "TC - V1.6" at 5.8,4.25 h1
  text "AN/JM" at 5.8,2.25 h1
  text "www.controlid.com.br" at 5.65,0.6 h1
Board Outline:
  lines w0.1: 6.2,95.6 0,95.6 0,5 1.5,5 1.5,1.5 4.5,1.5 5,1.5 5,0 48.6,0 50.6,0 50.6,1 52.6,3 53.6,3 53.6,5 53.6,95.6 47.4,95.6 47.4,100 26.8,100 6.2,100 6.2,95.6 ; 6.2,95.6 6.2,95.6
Dimensions:
  lines w0.1: 6.2,95.6 6.2,100 26.8,100 47.4,100 47.4,95.6 53.6,95.6 53.6,5 53.6,3 52.6,3 50.6,1 50.6,0 48.6,0 5,0 5,1.5 4.5,1.5 1.5,1.5 1.5,5 0,5 0,95.6 6.2,95.6 ; 6.2,95.6 6.2,95.6
Mechanical 86:
  lines w0.203: 0,5 5,5

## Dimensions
52.1,86 to 53.6,95.6 on Dimensions
0,3 to 53.6,3 on Dimensions
4,8.2 to 6.2,100 on Dimensions
6.2,100 to 4,3 on Dimensions
49.6,92.6 to 47.756,100 on Dimensions
52.1,86 to 47.756,100 on Dimensions
44.3,78 to 47.4,100 on Dimensions
44.3,60.5 to 47.756,100 on Dimensions
44.3,43 to 47.756,100 on Dimensions
44.3,25.5 to 47.4,100 on Dimensions
52,20.9 to 47.756,100 on Dimensions
26.8,8.5 to 47.4,100 on Dimensions
49.6,4.5 to 47.4,100 on Dimensions
4,3 to 49.6,4.5 on Dimensions
48.6,0 to 47.4,100 on Dimensions
47.4,100 to 53.6,95.6 on Dimensions
6.2,100 to 47.4,100 on Dimensions
1.5,1.5 to 5,1.5 on Dimensions
1.5,1.5 to 5,0 on Dimensions
1.5,5 to 1.5,1.5 on Dimensions
0,5 to 1.5,5 on Dimensions
50.6,0 to 50.6,1 on Dimensions
52.6,3 to 53.6,3 on Dimensions
6.2,100 to 11.56,94.7 on Dimensions
6.2,100 to 16.86,89.2 on Dimensions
